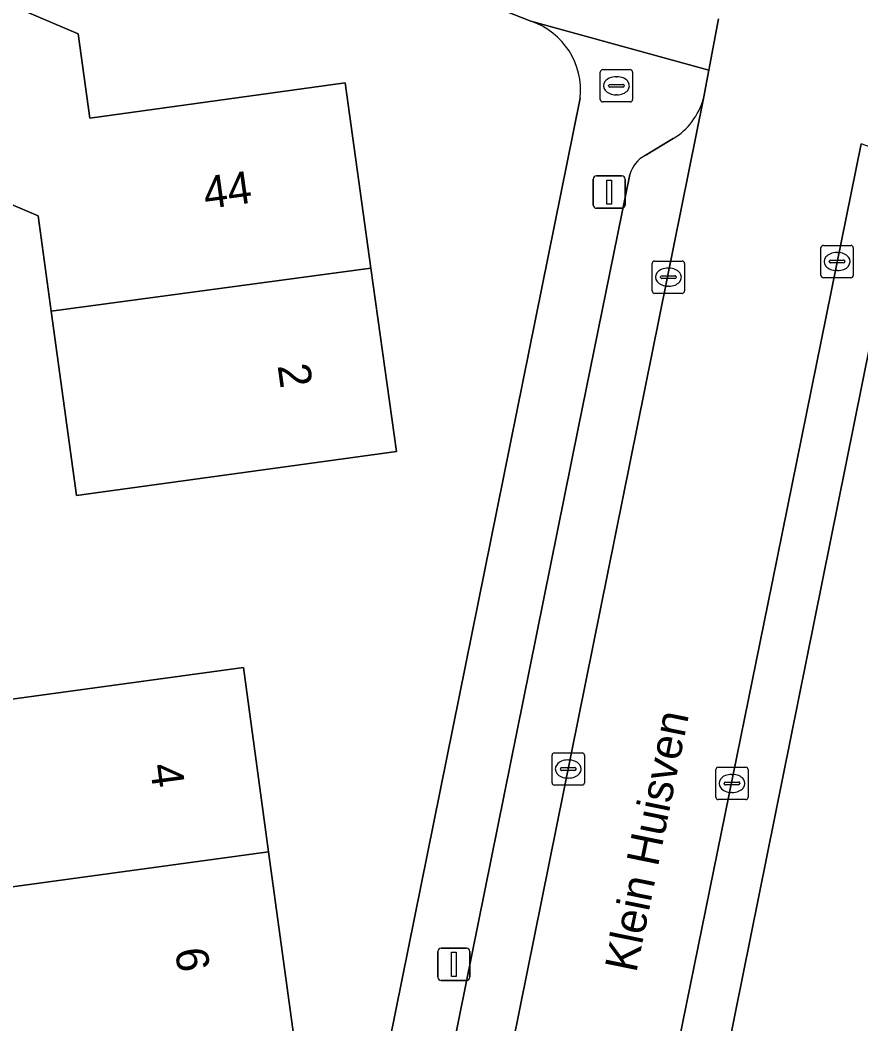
# Model space of a CAD drawing. Extents: x 163426 to 164192, y 380329 to 381641.
# Drawn here: x 163677.89 to 163703.91, y 381464.45 to 381495.51 of the extents above; entities that cross this region are included whole.
import ezdxf

# ---------------------------------------------------------------- set-up
doc = ezdxf.new("R2010")
doc.units = 0
for name, color, linetype in [('IMGEO_Brandkraan', 7, 'Continuous'), ('IMGEO_Erf', 7, 'Continuous'), ('IMGEO_Kolk', 7, 'Continuous'), ('IMGEO_Lichtmast', 7, 'Continuous'), ('IMGEO_Openbare_ruimte_label', 7, 'Continuous'), ('IMGEO_Pand', 7, 'Continuous'), ('IMGEO_Pand_nummerreeks', 7, 'Continuous'), ('IMGEO_Parkeervlak_open', 7, 'Continuous'), ('IMGEO_Rijbaan_lokaal_open', 7, 'Continuous'), ('IMGEO_Voetpad_open', 7, 'Continuous')]:
    doc.layers.add(name, color=color, linetype=linetype)

msp = doc.modelspace()

# ---------------------------------------------------------------- linework, layer by layer
at = {"layer": 'IMGEO_Brandkraan'}
for p, q in [((163695.846, 381493.049), (163695.846, 381493.901)), ((163695.921, 381493.975), (163696.773, 381493.975)), ((163696.847, 381493.901), (163696.847, 381493.049)), ((163696.334, 381493.755), (163696.359, 381493.755)), ((163696.105, 381493.469), (163696.105, 381493.481)), ((163696.543, 381493.432), (163696.145, 381493.432)), ((163696.148, 381493.518), (163696.546, 381493.518)), ((163696.589, 381493.481), (163696.589, 381493.469)), ((163696.773, 381492.975), (163695.921, 381492.975)), ((163696.357, 381493.195), (163696.332, 381493.195))]:
    msp.add_line(p, q, dxfattribs=at)
for points in [[(163695.846, 381493.049), (163695.846, 381493.901)], [(163695.921, 381493.975), (163696.773, 381493.975)], [(163696.847, 381493.901), (163696.847, 381493.049)], [(163696.773, 381492.975), (163695.921, 381492.975)]]:
    msp.add_lwpolyline(points, dxfattribs=at)
for centre, radius, start, end in [((163695.923, 381493.899), 0.0765, 91.552, 178.448), ((163695.923, 381493.899), 0.0765, 91.552, 178.448), ((163696.771, 381493.899), 0.0765, 1.552, 88.448), ((163696.771, 381493.899), 0.0765, 1.552, 88.448), ((163696.145, 381493.478), 0.0403, 85.8775, 175.7526), ((163696.142, 381493.468), 0.0366, 178.938, 274.7102), ((163696.546, 381493.475), 0.043, 264.8664, 352.4533), ((163696.55, 381493.48), 0.0386, 1.7309, 96.639), ((163695.923, 381493.051), 0.0765, 181.552, 268.448), ((163695.923, 381493.051), 0.0765, 181.552, 268.448), ((163696.771, 381493.051), 0.0765, 271.552, 358.448), ((163696.771, 381493.051), 0.0765, 271.552, 358.448)]:
    msp.add_arc(centre, radius, start, end, dxfattribs=at)
for centre, major_axis, ratio, start_param, end_param in [((163696.333, 381493.475), (-0.387, 0.002), 0.722429, 4.712389, 7.853982), ((163696.358, 381493.475), (-0.39, 0.002), 0.717154, 1.570796, 4.712389)]:
    msp.add_ellipse(centre, major_axis=major_axis, ratio=ratio, start_param=start_param, end_param=end_param, dxfattribs=at)
at = {"layer": 'IMGEO_Erf'}
for points in [[(163693.701, 381495.474), (163688.858, 381497.386), (163681.342, 381500)], [(163684.586, 381440.475), (163695.226, 381493.095)], [(163704.928, 381489.108), (163697.071, 381450.146), (163694.232, 381436.07)]]:
    msp.add_lwpolyline(points, dxfattribs=at)
for points in [[(163679.633, 381480.802), (163678.852, 381486.498), (163678.447, 381489.45), (163674.46, 381491.14), (163675.24, 381492.92), (163671.134, 381494.655), (163672.59, 381498.1), (163679.69, 381495.08), (163680.05, 381492.47), (163687.949, 381493.568), (163688.749, 381487.832), (163689.54, 381482.16), (163684.587, 381481.481)], [(163671.647, 381467.942), (163670.472, 381476.544), (163670.219, 381476.509), (163669.784, 381479.692), (163676.72, 381480.639), (163677.154, 381477.46), (163677.56, 381474.486), (163684.803, 381475.475), (163685.582, 381469.773), (163686.362, 381464.061), (163681.408, 381463.385), (163676.454, 381462.708), (163675.674, 381468.42), (163675.664, 381468.491)]]:
    msp.add_lwpolyline(points, close=True, dxfattribs=at)
msp.add_arc((163692.983, 381493.335), 2.256, 353.8853, 71.4366, dxfattribs=at)
at = {"layer": 'IMGEO_Kolk'}
for p, q in [((163702.675, 381487.61), (163702.675, 381488.462)), ((163702.75, 381488.536), (163703.602, 381488.536)), ((163703.163, 381488.316), (163703.188, 381488.316)), ((163703.676, 381488.462), (163703.676, 381487.61)), ((163697.455, 381487.127), (163697.455, 381487.979)), ((163697.53, 381488.053), (163698.382, 381488.053)), ((163698.456, 381487.979), (163698.456, 381487.127)), ((163702.934, 381488.03), (163702.934, 381488.042)), ((163703.372, 381487.993), (163702.974, 381487.993)), ((163702.977, 381488.079), (163703.375, 381488.079)), ((163703.418, 381488.042), (163703.418, 381488.03)), ((163697.943, 381487.833), (163697.968, 381487.833)), ((163703.186, 381487.756), (163703.161, 381487.756)), ((163697.714, 381487.547), (163697.714, 381487.559)), ((163698.152, 381487.51), (163697.754, 381487.51)), ((163697.757, 381487.596), (163698.155, 381487.596)), ((163698.198, 381487.559), (163698.198, 381487.547)), ((163703.602, 381487.536), (163702.75, 381487.536)), ((163698.382, 381487.053), (163697.53, 381487.053)), ((163697.966, 381487.273), (163697.941, 381487.273)), ((163694.355, 381471.908), (163694.355, 381472.76)), ((163694.43, 381472.834), (163695.282, 381472.834)), ((163695.356, 381472.76), (163695.356, 381471.908)), ((163694.843, 381472.614), (163694.868, 381472.614)), ((163694.614, 381472.328), (163694.614, 381472.34)), ((163695.052, 381472.291), (163694.654, 381472.291)), ((163694.657, 381472.377), (163695.055, 381472.377)), ((163695.098, 381472.34), (163695.098, 381472.328)), ((163699.422, 381471.462), (163699.422, 381472.314)), ((163699.497, 381472.388), (163700.349, 381472.388)), ((163699.91, 381472.168), (163699.935, 381472.168)), ((163700.423, 381472.314), (163700.423, 381471.462)), ((163695.282, 381471.834), (163694.43, 381471.834)), ((163694.866, 381472.054), (163694.841, 381472.054)), ((163699.681, 381471.882), (163699.681, 381471.894)), ((163700.119, 381471.845), (163699.721, 381471.845)), ((163699.724, 381471.931), (163700.122, 381471.931)), ((163700.165, 381471.894), (163700.165, 381471.882)), ((163699.933, 381471.608), (163699.908, 381471.608)), ((163700.349, 381471.388), (163699.497, 381471.388))]:
    msp.add_line(p, q, dxfattribs=at)
for points in [[(163702.675, 381487.61), (163702.675, 381488.462)], [(163702.75, 381488.536), (163703.602, 381488.536)], [(163703.676, 381488.462), (163703.676, 381487.61)], [(163697.455, 381487.127), (163697.455, 381487.979)], [(163697.53, 381488.053), (163698.382, 381488.053)], [(163698.456, 381487.979), (163698.456, 381487.127)], [(163703.602, 381487.536), (163702.75, 381487.536)], [(163698.382, 381487.053), (163697.53, 381487.053)], [(163694.355, 381471.908), (163694.355, 381472.76)], [(163694.43, 381472.834), (163695.282, 381472.834)], [(163695.356, 381472.76), (163695.356, 381471.908)], [(163699.422, 381471.462), (163699.422, 381472.314)], [(163699.497, 381472.388), (163700.349, 381472.388)], [(163700.423, 381472.314), (163700.423, 381471.462)], [(163695.282, 381471.834), (163694.43, 381471.834)], [(163700.349, 381471.388), (163699.497, 381471.388)]]:
    msp.add_lwpolyline(points, dxfattribs=at)
for centre, radius, start, end in [((163702.752, 381488.46), 0.0765, 91.552, 178.448), ((163702.752, 381488.46), 0.0765, 91.552, 178.448), ((163703.6, 381488.46), 0.0765, 1.552, 88.448), ((163703.6, 381488.46), 0.0765, 1.552, 88.448), ((163697.532, 381487.977), 0.0765, 91.552, 178.448), ((163697.532, 381487.977), 0.0765, 91.552, 178.448), ((163698.38, 381487.977), 0.0765, 1.552, 88.448), ((163698.38, 381487.977), 0.0765, 1.552, 88.448), ((163702.974, 381488.039), 0.0403, 85.8775, 175.7526), ((163702.971, 381488.029), 0.0366, 178.938, 274.7102), ((163703.375, 381488.036), 0.043, 264.8664, 352.4533), ((163703.379, 381488.041), 0.0386, 1.7309, 96.639), ((163697.754, 381487.556), 0.0403, 85.8775, 175.7526), ((163697.751, 381487.546), 0.0366, 178.938, 274.7102), ((163698.155, 381487.553), 0.043, 264.8664, 352.4533), ((163698.159, 381487.558), 0.0386, 1.7309, 96.639), ((163702.752, 381487.612), 0.0765, 181.552, 268.448), ((163702.752, 381487.612), 0.0765, 181.552, 268.448), ((163703.6, 381487.612), 0.0765, 271.552, 358.448), ((163703.6, 381487.612), 0.0765, 271.552, 358.448), ((163697.532, 381487.129), 0.0765, 181.552, 268.448), ((163697.532, 381487.129), 0.0765, 181.552, 268.448), ((163698.38, 381487.129), 0.0765, 271.552, 358.448), ((163698.38, 381487.129), 0.0765, 271.552, 358.448), ((163694.432, 381472.758), 0.0765, 91.552, 178.448), ((163694.432, 381472.758), 0.0765, 91.552, 178.448), ((163695.28, 381472.758), 0.0765, 1.552, 88.448), ((163695.28, 381472.758), 0.0765, 1.552, 88.448), ((163694.654, 381472.337), 0.0403, 85.8775, 175.7526), ((163694.651, 381472.327), 0.0366, 178.938, 274.7102), ((163695.055, 381472.334), 0.043, 264.8664, 352.4533), ((163695.059, 381472.339), 0.0386, 1.7309, 96.639), ((163699.499, 381472.312), 0.0765, 91.552, 178.448), ((163699.499, 381472.312), 0.0765, 91.552, 178.448), ((163700.347, 381472.312), 0.0765, 1.552, 88.448), ((163700.347, 381472.312), 0.0765, 1.552, 88.448), ((163694.432, 381471.91), 0.0765, 181.552, 268.448), ((163694.432, 381471.91), 0.0765, 181.552, 268.448), ((163695.28, 381471.91), 0.0765, 271.552, 358.448), ((163695.28, 381471.91), 0.0765, 271.552, 358.448), ((163699.721, 381471.891), 0.0403, 85.8775, 175.7526), ((163699.718, 381471.881), 0.0366, 178.938, 274.7102), ((163700.122, 381471.888), 0.043, 264.8664, 352.4533), ((163700.126, 381471.893), 0.0386, 1.7309, 96.639), ((163699.499, 381471.464), 0.0765, 181.552, 268.448), ((163699.499, 381471.464), 0.0765, 181.552, 268.448), ((163700.347, 381471.464), 0.0765, 271.552, 358.448), ((163700.347, 381471.464), 0.0765, 271.552, 358.448)]:
    msp.add_arc(centre, radius, start, end, dxfattribs=at)
for centre, major_axis, ratio, start_param, end_param in [((163703.162, 381488.036), (-0.387, 0.002), 0.722429, 4.712389, 7.853982), ((163703.187, 381488.036), (-0.39, 0.002), 0.717154, 1.570796, 4.712389), ((163697.942, 381487.553), (-0.387, 0.002), 0.722429, 4.712389, 7.853982), ((163697.967, 381487.553), (-0.39, 0.002), 0.717154, 1.570796, 4.712389), ((163694.842, 381472.334), (-0.387, 0.002), 0.722429, 4.712389, 7.853982), ((163694.867, 381472.334), (-0.39, 0.002), 0.717154, 1.570796, 4.712389), ((163699.909, 381471.888), (-0.387, 0.002), 0.722429, 4.712389, 7.853982), ((163699.934, 381471.888), (-0.39, 0.002), 0.717154, 1.570796, 4.712389)]:
    msp.add_ellipse(centre, major_axis=major_axis, ratio=ratio, start_param=start_param, end_param=end_param, dxfattribs=at)
at = {"layer": 'IMGEO_Lichtmast'}
for p, q in [((163695.627, 381489.785), (163695.627, 381490.585)), ((163695.627, 381490.585), (163695.627, 381489.785)), ((163695.727, 381490.685), (163696.517, 381490.685)), ((163696.517, 381490.685), (163695.727, 381490.685)), ((163696.617, 381490.585), (163696.617, 381489.785)), ((163696.617, 381489.785), (163696.617, 381490.585)), ((163696.517, 381489.685), (163695.727, 381489.685)), ((163695.727, 381489.685), (163696.517, 381489.685)), ((163690.819, 381465.89), (163690.819, 381466.69)), ((163690.819, 381466.69), (163690.819, 381465.89)), ((163690.919, 381466.79), (163691.709, 381466.79)), ((163691.709, 381466.79), (163690.919, 381466.79)), ((163691.809, 381466.69), (163691.809, 381465.89)), ((163691.809, 381465.89), (163691.809, 381466.69)), ((163691.709, 381465.79), (163690.919, 381465.79)), ((163690.919, 381465.79), (163691.709, 381465.79))]:
    msp.add_line(p, q, dxfattribs=at)
for points in [[(163696.047, 381490.56), (163696.197, 381490.56), (163696.197, 381489.81), (163696.047, 381489.81), (163696.047, 381490.56)], [(163691.239, 381466.665), (163691.389, 381466.665), (163691.389, 381465.915), (163691.239, 381465.915), (163691.239, 381466.665)]]:
    msp.add_lwpolyline(points, dxfattribs=at)
for centre, start, end in [((163695.727, 381490.585), 90, 180), ((163695.727, 381490.585), 90, 180), ((163696.517, 381490.585), 0, 90), ((163696.517, 381490.585), 360, 90), ((163695.727, 381489.785), 180, 270), ((163695.727, 381489.785), 180, 270), ((163696.517, 381489.785), 270, 0), ((163696.517, 381489.785), 270, 0), ((163690.919, 381466.69), 90, 180), ((163690.919, 381466.69), 90, 180), ((163691.709, 381466.69), 0, 90), ((163691.709, 381466.69), 360, 90), ((163690.919, 381465.89), 180, 270), ((163690.919, 381465.89), 180, 270), ((163691.709, 381465.89), 270, 0), ((163691.709, 381465.89), 270, 0)]:
    msp.add_arc(centre, 0.1, start, end, dxfattribs=at)
at = {"layer": 'IMGEO_Pand'}
for points in [[(163688.749, 381487.832), (163687.949, 381493.568), (163680.05, 381492.47), (163679.69, 381495.08), (163672.59, 381498.1), (163671.134, 381494.655), (163675.24, 381492.92), (163674.46, 381491.14), (163678.447, 381489.45), (163678.852, 381486.498)], [(163688.749, 381487.832), (163678.852, 381486.498), (163679.633, 381480.802), (163684.587, 381481.481), (163689.54, 381482.16)], [(163684.803, 381475.475), (163677.56, 381474.486), (163677.154, 381477.46), (163670.472, 381476.544), (163671.647, 381467.942), (163675.664, 381468.491), (163675.674, 381468.42), (163685.582, 381469.773)], [(163685.582, 381469.773), (163675.674, 381468.42), (163676.454, 381462.708), (163681.408, 381463.385), (163686.362, 381464.061)]]:
    msp.add_lwpolyline(points, close=True, dxfattribs=at)
at = {"layer": 'IMGEO_Parkeervlak_open'}
for points in [[(163688.349, 381440.137), (163699.036, 381493.078)], [(163698.101, 381491.84), (163697.238, 381491.322)], [(163696.758, 381490.726), (163695.167, 381482.868), (163693.669, 381475.469), (163691.479, 381464.649), (163689.983, 381457.257), (163687.126, 381443.145)]]:
    msp.add_lwpolyline(points, dxfattribs=at)
for centre, radius, start, end in [((163697.023, 381493.626), 2.086, 301.1063, 344.7698), ((163697.704, 381490.456), 0.984, 118.263, 164.0432)]:
    msp.add_arc(centre, radius, start, end, dxfattribs=at)
at = {"layer": 'IMGEO_Rijbaan_lokaal_open'}
for points in [[(163699.502, 381495.543), (163699.203, 381493.959), (163699.036, 381493.078), (163688.349, 381440.137), (163688.227, 381439.533)], [(163692.72, 381436.391), (163695.952, 381452.495), (163696.258, 381453.943), (163696.763, 381456.371), (163697.912, 381462.127), (163701.036, 381477.436), (163702.541, 381484.864), (163703.922, 381491.677)]]:
    msp.add_lwpolyline(points, dxfattribs=at)
at = {"layer": 'IMGEO_Voetpad_open'}
for points in [[(163681.342, 381500), (163688.858, 381497.386), (163693.701, 381495.474), (163699.203, 381493.959), (163699.502, 381495.543)], [(163699.036, 381493.078), (163699.203, 381493.959), (163693.701, 381495.474)], [(163695.226, 381493.095), (163684.586, 381440.475), (163688.227, 381439.533), (163688.349, 381440.137)], [(163697.238, 381491.322), (163698.101, 381491.84)], [(163707.206, 381490.503), (163703.922, 381491.677), (163702.541, 381484.864), (163701.036, 381477.436), (163697.912, 381462.127), (163696.763, 381456.371), (163696.258, 381453.943), (163695.952, 381452.495), (163692.72, 381436.391)], [(163693.669, 381475.469), (163695.167, 381482.868), (163696.758, 381490.726)], [(163694.232, 381436.07), (163697.071, 381450.146), (163704.928, 381489.108)], [(163687.126, 381443.145), (163689.983, 381457.257), (163691.479, 381464.649), (163693.669, 381475.469)]]:
    msp.add_lwpolyline(points, dxfattribs=at)
for centre, radius, start, end in [((163692.983, 381493.335), 2.256, 353.8853, 71.4366), ((163697.023, 381493.626), 2.086, 301.1063, 344.7698), ((163697.704, 381490.456), 0.984, 118.263, 164.0432)]:
    msp.add_arc(centre, radius, start, end, dxfattribs=at)

# ---------------------------------------------------------------- texts
at = {"layer": 'IMGEO_Openbare_ruimte_label'}
msp.add_text('Klein Huisven', height=1, rotation=78.4654, dxfattribs=at).set_placement((163696.959, 381466.006))
at = {"layer": 'IMGEO_Pand_nummerreeks'}
for s, rotation, p in [('44', 7.9137, (163683.633, 381489.657)), ('2', 277.9395, (163685.858, 381484.818)), ('4', 277.7806, (163681.904, 381472.451)), ('6', 277.7777, (163682.685, 381466.743))]:
    msp.add_text(s, height=1, rotation=rotation, dxfattribs=at).set_placement(p)

doc.saveas('drawing.dxf')
